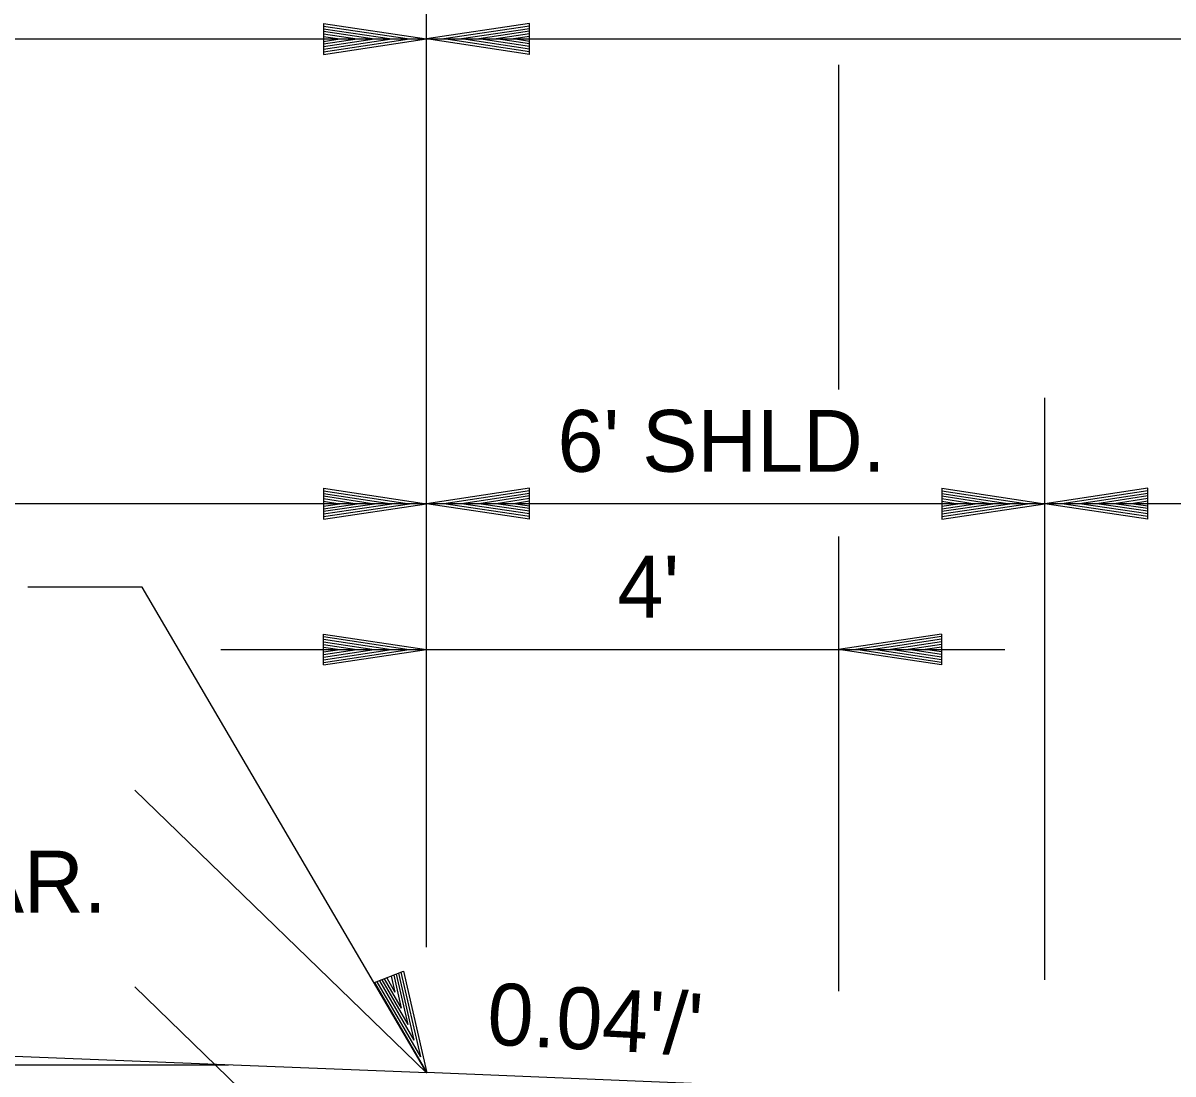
# Model space of a CAD drawing. Extents: x 1955768 to 1955917, y 566446 to 566546.
# Drawn here: x 1955847.75 to 1955858.92, y 566519.66 to 566529.86 of the extents above; entities that cross this region are included whole.
import ezdxf

# ---------------------------------------------------------------- set-up
doc = ezdxf.new("R2010")
doc.units = 0
doc.layers.add('R_Border', color=7, linetype='Continuous')
doc.layers.add('R_Grid', color=7, linetype='Continuous')

msp = doc.modelspace()

# ---------------------------------------------------------------- linework, layer by layer
at = {"layer": 'R_Border'}
for p, q in [((1955851.672, 566519.668), (1955848.84, 566522.413)), ((1955851.672, 566517.757), (1955848.84, 566520.502)), ((1955851.673, 566519.668), (1955839.673, 566520.148)), ((1955841.248, 566519.745), (1955849.75, 566519.745)), ((1955857.672, 566519.421), (1955851.672, 566519.67))]:
    msp.add_line(p, q, dxfattribs=at)
at = {"layer": 'R_Grid'}
for p, q in [((1955851.672, 566520.889), (1955851.672, 566535.038)), ((1955850.672, 566529.858), (1955851.672, 566529.708)), ((1955850.672, 566529.858), (1955850.672, 566529.558)), ((1955850.672, 566529.833), (1955851.505, 566529.708)), ((1955852.672, 566529.858), (1955851.672, 566529.708)), ((1955852.672, 566529.833), (1955851.839, 566529.708)), ((1955852.672, 566529.558), (1955852.672, 566529.858)), ((1955850.672, 566529.807), (1955851.333, 566529.708)), ((1955850.672, 566529.782), (1955851.167, 566529.708)), ((1955850.672, 566529.756), (1955850.997, 566529.708)), ((1955850.672, 566529.731), (1955850.83, 566529.708)), ((1955852.672, 566529.807), (1955852.011, 566529.708)), ((1955852.672, 566529.782), (1955852.178, 566529.708)), ((1955852.672, 566529.757), (1955852.347, 566529.708)), ((1955852.672, 566529.731), (1955852.514, 566529.708)), ((1955827.673, 566529.708), (1955851.672, 566529.708)), ((1955850.672, 566529.558), (1955851.672, 566529.708)), ((1955850.672, 566529.659), (1955850.997, 566529.708)), ((1955850.672, 566529.608), (1955851.333, 566529.708)), ((1955850.672, 566529.583), (1955851.505, 566529.708)), ((1955850.672, 566529.633), (1955851.167, 566529.708)), ((1955850.672, 566529.684), (1955850.83, 566529.708)), ((1955852.672, 566529.558), (1955851.672, 566529.708)), ((1955851.672, 566529.708), (1955881.672, 566529.708)), ((1955852.672, 566529.583), (1955851.839, 566529.708)), ((1955852.672, 566529.608), (1955852.011, 566529.708)), ((1955852.672, 566529.633), (1955852.178, 566529.708)), ((1955852.672, 566529.659), (1955852.347, 566529.708)), ((1955852.672, 566529.684), (1955852.514, 566529.708)), ((1955855.673, 566526.305), (1955855.673, 566529.458)), ((1955857.672, 566521.108), (1955857.672, 566526.223)), ((1955857.673, 566520.571), (1955857.673, 566525.497)), ((1955850.672, 566525.345), (1955851.672, 566525.195)), ((1955850.672, 566525.345), (1955850.672, 566525.045)), ((1955850.672, 566525.32), (1955851.505, 566525.195)), ((1955850.672, 566525.295), (1955851.333, 566525.195)), ((1955850.672, 566525.27), (1955851.167, 566525.195)), ((1955852.672, 566525.345), (1955851.672, 566525.195)), ((1955852.672, 566525.32), (1955851.839, 566525.195)), ((1955852.672, 566525.295), (1955852.011, 566525.195)), ((1955852.672, 566525.27), (1955852.178, 566525.195)), ((1955852.672, 566525.045), (1955852.672, 566525.345)), ((1955856.672, 566525.345), (1955857.672, 566525.195)), ((1955856.672, 566525.345), (1955856.672, 566525.045)), ((1955856.672, 566525.32), (1955857.505, 566525.195)), ((1955856.672, 566525.295), (1955857.333, 566525.195)), ((1955856.672, 566525.27), (1955857.167, 566525.195)), ((1955858.672, 566525.345), (1955857.672, 566525.195)), ((1955858.672, 566525.32), (1955857.839, 566525.195)), ((1955858.672, 566525.295), (1955858.011, 566525.195)), ((1955858.672, 566525.27), (1955858.178, 566525.195)), ((1955858.672, 566525.045), (1955858.672, 566525.345)), ((1955851.672, 566525.195), (1955839.673, 566525.195)), ((1955850.672, 566525.244), (1955850.997, 566525.195)), ((1955850.672, 566525.219), (1955850.83, 566525.195)), ((1955850.672, 566525.045), (1955851.672, 566525.195)), ((1955850.672, 566525.146), (1955850.997, 566525.195)), ((1955850.672, 566525.096), (1955851.333, 566525.195)), ((1955850.672, 566525.07), (1955851.505, 566525.195)), ((1955850.672, 566525.121), (1955851.167, 566525.195)), ((1955850.672, 566525.172), (1955850.83, 566525.195)), ((1955852.672, 566525.045), (1955851.672, 566525.195)), ((1955857.672, 566525.195), (1955851.672, 566525.195)), ((1955852.672, 566525.07), (1955851.839, 566525.195)), ((1955852.672, 566525.096), (1955852.011, 566525.195)), ((1955852.672, 566525.121), (1955852.178, 566525.195)), ((1955852.672, 566525.244), (1955852.347, 566525.195)), ((1955852.672, 566525.147), (1955852.347, 566525.195)), ((1955852.672, 566525.219), (1955852.514, 566525.195)), ((1955852.672, 566525.172), (1955852.514, 566525.195)), ((1955856.672, 566525.244), (1955856.997, 566525.195)), ((1955856.672, 566525.219), (1955856.83, 566525.195)), ((1955856.672, 566525.045), (1955857.672, 566525.195)), ((1955856.672, 566525.146), (1955856.997, 566525.195)), ((1955856.672, 566525.096), (1955857.333, 566525.195)), ((1955856.672, 566525.07), (1955857.505, 566525.195)), ((1955856.672, 566525.121), (1955857.167, 566525.195)), ((1955856.672, 566525.172), (1955856.83, 566525.195)), ((1955858.672, 566525.045), (1955857.672, 566525.195)), ((1955863.922, 566525.195), (1955857.672, 566525.195)), ((1955858.672, 566525.07), (1955857.839, 566525.195)), ((1955858.672, 566525.096), (1955858.011, 566525.195)), ((1955858.672, 566525.121), (1955858.178, 566525.195)), ((1955858.672, 566525.244), (1955858.347, 566525.195)), ((1955858.672, 566525.147), (1955858.347, 566525.195)), ((1955858.672, 566525.219), (1955858.514, 566525.195)), ((1955858.672, 566525.172), (1955858.514, 566525.195)), ((1955855.672, 566520.462), (1955855.672, 566524.877)), ((1955850.67, 566523.929), (1955851.67, 566523.779)), ((1955850.67, 566523.629), (1955850.67, 566523.929)), ((1955856.671, 566523.929), (1955855.671, 566523.779)), ((1955856.671, 566523.929), (1955856.671, 566523.629)), ((1955850.67, 566523.904), (1955851.503, 566523.779)), ((1955850.67, 566523.879), (1955851.331, 566523.779)), ((1955850.67, 566523.854), (1955851.164, 566523.779)), ((1955850.67, 566523.828), (1955850.995, 566523.779)), ((1955850.67, 566523.803), (1955850.828, 566523.779)), ((1955856.671, 566523.904), (1955855.838, 566523.779)), ((1955856.671, 566523.879), (1955856.01, 566523.779)), ((1955856.671, 566523.854), (1955856.176, 566523.779)), ((1955856.671, 566523.828), (1955856.346, 566523.779)), ((1955856.671, 566523.803), (1955856.513, 566523.779)), ((1955849.673, 566523.779), (1955851.671, 566523.779)), ((1955850.67, 566523.629), (1955851.67, 566523.779)), ((1955850.67, 566523.731), (1955850.995, 566523.779)), ((1955850.67, 566523.68), (1955851.331, 566523.779)), ((1955850.67, 566523.654), (1955851.503, 566523.779)), ((1955850.67, 566523.705), (1955851.164, 566523.779)), ((1955850.67, 566523.756), (1955850.828, 566523.779)), ((1955851.672, 566523.779), (1955855.67, 566523.779)), ((1955855.286, 566523.779), (1955857.285, 566523.779)), ((1955856.671, 566523.629), (1955855.671, 566523.779)), ((1955856.671, 566523.654), (1955855.838, 566523.779)), ((1955856.671, 566523.68), (1955856.01, 566523.779)), ((1955856.671, 566523.705), (1955856.176, 566523.779)), ((1955856.671, 566523.73), (1955856.346, 566523.779)), ((1955856.671, 566523.756), (1955856.513, 566523.779)), ((1955851.167, 566520.544), (1955851.446, 566520.654)), ((1955851.214, 566520.562), (1955851.549, 566519.984)), ((1955851.237, 566520.571), (1955851.488, 566520.139)), ((1955851.261, 566520.581), (1955851.425, 566520.296)), ((1955851.284, 566520.59), (1955851.364, 566520.452)), ((1955851.328, 566520.607), (1955851.364, 566520.452)), ((1955851.352, 566520.617), (1955851.425, 566520.296)), ((1955851.376, 566520.626), (1955851.488, 566520.139)), ((1955851.399, 566520.635), (1955851.549, 566519.984)), ((1955851.423, 566520.645), (1955851.612, 566519.824)), ((1955851.446, 566520.654), (1955851.673, 566519.668)), ((1955851.167, 566520.544), (1955851.673, 566519.668)), ((1955851.19, 566520.553), (1955851.612, 566519.824))]:
    msp.add_line(p, q, dxfattribs=at)
msp.add_lwpolyline([(1955851.673, 566519.668), (1955848.912, 566524.383), (1955847.801, 566524.383)], dxfattribs=at)

# ---------------------------------------------------------------- texts
at = {"layer": 'R_Border'}
for s, p in [("6' SHLD.", (1955852.943, 566525.505)), ("4'", (1955853.525, 566524.089)), ('VAR.', (1955846.693, 566521.225))]:
    msp.add_text(s, height=0.6, dxfattribs=at).set_placement(p)
msp.add_text("0.04'/'", height=0.6, rotation=356.9953, dxfattribs=at).set_placement((1955852.249, 566519.945))

doc.saveas('drawing.dxf')
